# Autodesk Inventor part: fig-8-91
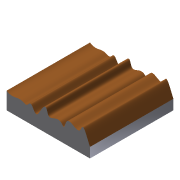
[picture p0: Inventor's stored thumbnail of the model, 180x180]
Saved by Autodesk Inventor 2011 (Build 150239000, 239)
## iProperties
Shininess: 64.0
Length Units: 11269
Angle Units: 11279
Time Units: 11290
Mass Units: 11283
Length Display Precision: 3
Angle Display Precision: 2
Compacted: True
Part Number: fig-8-91
Document SubType Name: Modeling
Created: 2002-12
Designer: deepak
Density: 1 g/cm^3
Density: 0.0
Volumn: 0.0
Area: 0.0
PropertySet Name: Model Information
Control State: 0
Master: False
Checked Out: False
Author: deepak
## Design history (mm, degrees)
sketch "Sketch1"
  geometry: L1 (-32.188, 30.089)-(27.812, 30.089); L2 (27.812, 30.089)-(27.812, -29.911); L3 (27.812, -29.911)-(-32.188, -29.911); L4 (-32.188, -29.911)-(-32.188, 30.089)
  constraints: 8 end point, 2 parallel, 1 horizontal, 1 perpendicular
  dimensions: "d0" = 60 distance of L1.start L1.end; "d1" = 60 distance of L3.end L1.start
extrude "Extrusion1" new body sketch "Sketch1" stored distance "d2" = 20; taper "d3" = 0 deg
sketch "Sketch2"
  geometry: 17 further points
  constraints: 17 other
extrude_surface "ExtrusionSrf1" sketch "Sketch2" dims "d4" = 70, "d5" = 0
split "Split1"
body "Solid1"
body "Srf1"
